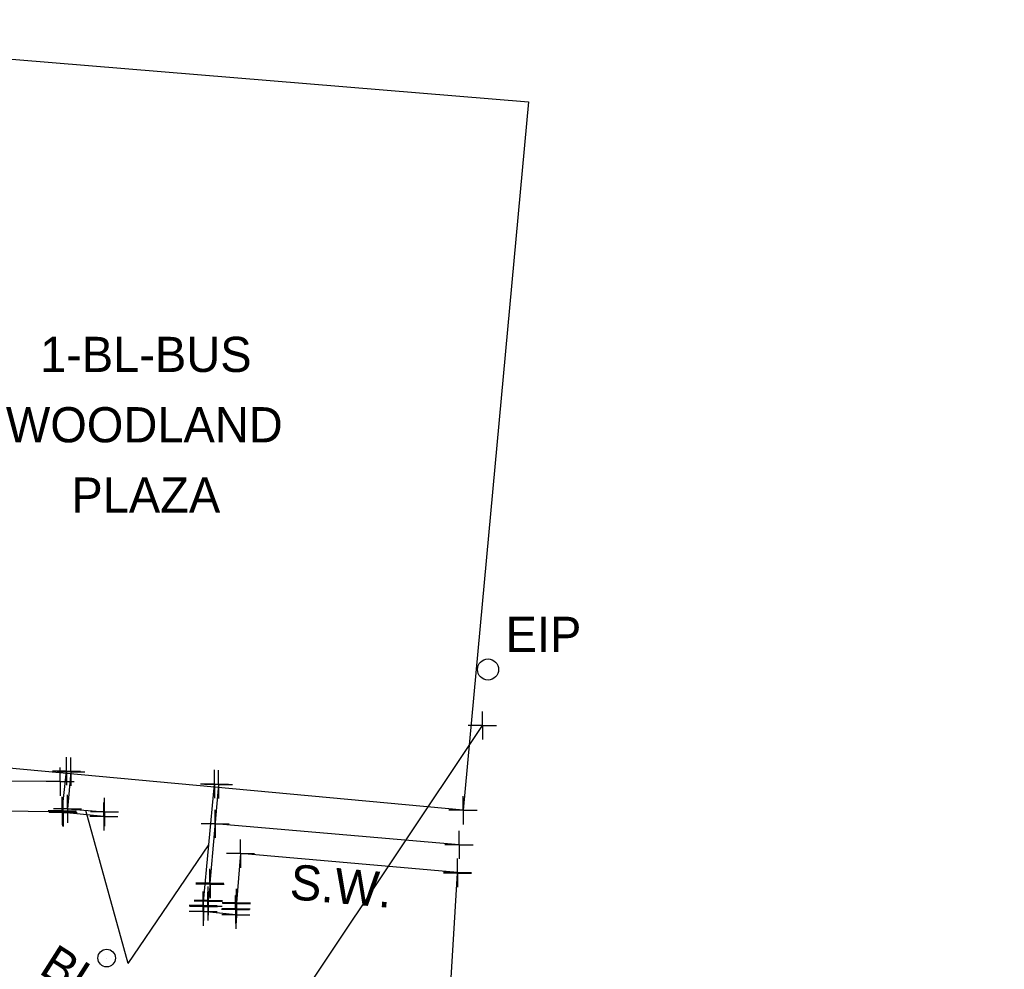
# Model space of a CAD drawing. Extents: x 0 to 1944463, y 0 to 420651.
# Drawn here: x 1942891.8 to 1943031.9, y 417869.6 to 418004.6 of the extents above; entities that cross this region are included whole.
import ezdxf

# ---------------------------------------------------------------- set-up
doc = ezdxf.new("R2010")
doc.units = 0
for name, color, linetype in [('SUR - DTM - Breaklines', 7, 'Continuous'), ('SUR - DTM - Breaklines - Points - Locators', 7, 'Continuous'), ('SUR - DTM - Spot Points - Locators', 7, 'Continuous'), ('SUR - NON-TRAN - Buildings', 7, 'Continuous'), ('SUR - NON-TRAN - Buildings - Points - Locators', 7, 'Continuous'), ('SUR - NON-TRAN - Buildings Text', 7, 'Continuous'), ('SUR - NON-TRAN - Features', 7, 'Continuous'), ('SUR - NON-TRAN - Features - Points - Locators', 7, 'Continuous'), ('SUR - NON-TRAN - Features Text', 7, 'Continuous'), ('SUR - PROPERTY - Property Markers', 7, 'Continuous'), ('SUR - TRAN - Features', 7, 'Continuous'), ('SUR - TRAN - Features - Points - Locators', 7, 'Continuous'), ('SUR - UTL - Overhead Wire Crossings', 7, 'Continuous'), ('SUR - UTL - Overhead Wire Crossings - Points - Locators', 7, 'Continuous')]:
    doc.layers.add(name, color=color, linetype=linetype)

msp = doc.modelspace()

# ---------------------------------------------------------------- linework, layer by layer
at = {"layer": 'SUR - DTM - Breaklines'}
for points in [[(1942903.8, 417891.31), (1942898.03, 417891.89), (1942897.89, 417892.1), (1942898.5, 417897.74)], [(1942920.11, 417895.87), (1942918.88, 417881.84), (1942918.91, 417881.69), (1942918.67, 417879.34), (1942918.67, 417879.26), (1942918.62, 417878.53)]]:
    msp.add_lwpolyline(points, dxfattribs=at)
at = {"layer": 'SUR - DTM - Breaklines - Points - Locators'}
for p, q in [((1942898.5, 417897.74), (1942898.5, 417899.74)), ((1942898.5, 417897.74), (1942896.5, 417897.74)), ((1942898.5, 417897.74), (1942900.5, 417897.74)), ((1942898.5, 417897.74), (1942898.5, 417895.74)), ((1942920.11, 417895.87), (1942920.11, 417897.87)), ((1942920.11, 417895.87), (1942918.11, 417895.87)), ((1942920.11, 417895.87), (1942922.11, 417895.87)), ((1942920.11, 417895.87), (1942920.11, 417893.87)), ((1942897.89, 417892.1), (1942897.89, 417894.1)), ((1942898.03, 417891.89), (1942898.03, 417893.89)), ((1942903.8, 417891.31), (1942903.8, 417893.31)), ((1942897.89, 417892.1), (1942895.89, 417892.1)), ((1942898.03, 417891.89), (1942896.03, 417891.89)), ((1942897.89, 417892.1), (1942899.89, 417892.1)), ((1942897.89, 417892.1), (1942897.89, 417890.1)), ((1942898.03, 417891.89), (1942900.03, 417891.89)), ((1942898.03, 417891.89), (1942898.03, 417889.89)), ((1942903.8, 417891.31), (1942901.8, 417891.31)), ((1942903.8, 417891.31), (1942905.8, 417891.31)), ((1942903.8, 417891.31), (1942903.8, 417889.31)), ((1942918.88, 417881.84), (1942918.88, 417883.84)), ((1942918.91, 417881.69), (1942918.91, 417883.69)), ((1942918.88, 417881.84), (1942916.88, 417881.84)), ((1942918.91, 417881.69), (1942916.91, 417881.69)), ((1942918.67, 417879.34), (1942918.67, 417881.34)), ((1942918.67, 417879.26), (1942918.67, 417881.26)), ((1942918.88, 417881.84), (1942920.88, 417881.84)), ((1942918.88, 417881.84), (1942918.88, 417879.84)), ((1942918.91, 417881.69), (1942920.91, 417881.69)), ((1942918.91, 417881.69), (1942918.91, 417879.69)), ((1942918.67, 417879.34), (1942916.67, 417879.34)), ((1942918.67, 417879.26), (1942916.67, 417879.26)), ((1942918.62, 417878.53), (1942918.62, 417880.53)), ((1942918.67, 417879.34), (1942920.67, 417879.34)), ((1942918.67, 417879.34), (1942918.67, 417877.34)), ((1942918.67, 417879.26), (1942920.67, 417879.26)), ((1942918.67, 417879.26), (1942918.67, 417877.26)), ((1942918.62, 417878.53), (1942916.62, 417878.53)), ((1942918.62, 417878.53), (1942920.62, 417878.53)), ((1942918.62, 417878.53), (1942918.62, 417876.53))]:
    msp.add_line(p, q, dxfattribs=at)
at = {"layer": 'SUR - DTM - Spot Points - Locators'}
msp.add_line((1942904.22, 417871.16), (1942904.22, 417871.16), dxfattribs=at)
msp.add_circle((1942904.21, 417871.17), 1.25, dxfattribs=at)
at = {"layer": 'SUR - NON-TRAN - Buildings'}
msp.add_lwpolyline([(1942954.9, 417892.18), (1942856.97, 417901.23), (1942856.04, 417902.23), (1942856.11, 417903.16), (1942856.72, 417903.14), (1942864.84, 418001.13), (1942964.21, 417992.89)], close=True, dxfattribs=at)
at = {"layer": 'SUR - NON-TRAN - Buildings - Points - Locators'}
for q in [(1942954.9, 417894.18), (1942952.9, 417892.18), (1942956.9, 417892.18), (1942954.9, 417890.18)]:
    msp.add_line((1942954.9, 417892.18), q, dxfattribs=at)
at = {"layer": 'SUR - NON-TRAN - Features'}
for points in [[(1942897.92, 417891.94), (1942849.1, 417892.44), (1942840.15, 417898.52), (1942826.26, 417915.06), (1942801.69, 417944.46), (1942786.47, 417977.69), (1942788.63, 418004.59)], [(1942897.61, 417896.26), (1942849.2, 417896.39), (1942849.2, 417899.01), (1942841.88, 417900.04), (1942844.3, 417902.13), (1942830.35, 417918.22), (1942805.44, 417947.15), (1942791.55, 417977.18), (1942794.14, 418004.51)], [(1942899.12, 417897.67), (1942898.65, 417892.4), (1942903.89, 417891.94)], [(1942917.94, 417878.66), (1942919.54, 417895.92)], [(1942954.33, 417887.28), (1942919.63, 417890.25)], [(1942954.12, 417883.34), (1942923.25, 417886.02), (1942922.66, 417879.01), (1942922.68, 417878.91), (1942922.61, 417878.16), (1942922.55, 417878.08), (1942922.58, 417877.31), (1942917.93, 417877.77), (1942917.99, 417878.51)]]:
    msp.add_lwpolyline(points, dxfattribs=at)
at = {"layer": 'SUR - NON-TRAN - Features - Points - Locators'}
for p, q in [((1942899.12, 417897.67), (1942899.12, 417899.67)), ((1942899.12, 417897.67), (1942897.12, 417897.67)), ((1942897.61, 417896.26), (1942897.61, 417898.26)), ((1942899.12, 417897.67), (1942901.12, 417897.67)), ((1942899.12, 417897.67), (1942899.12, 417895.67)), ((1942919.54, 417895.92), (1942919.54, 417897.92)), ((1942897.61, 417896.26), (1942895.61, 417896.26)), ((1942897.61, 417896.26), (1942899.61, 417896.26)), ((1942897.61, 417896.26), (1942897.61, 417894.26)), ((1942919.54, 417895.92), (1942917.54, 417895.92)), ((1942919.54, 417895.92), (1942921.54, 417895.92)), ((1942919.54, 417895.92), (1942919.54, 417893.92)), ((1942897.92, 417891.94), (1942897.92, 417893.94)), ((1942898.65, 417892.4), (1942898.65, 417894.4)), ((1942903.89, 417891.94), (1942903.89, 417893.94)), ((1942897.92, 417891.94), (1942895.92, 417891.94)), ((1942898.65, 417892.4), (1942896.65, 417892.4)), ((1942897.92, 417891.94), (1942899.92, 417891.94)), ((1942897.92, 417891.94), (1942897.92, 417889.94)), ((1942898.65, 417892.4), (1942900.65, 417892.4)), ((1942898.65, 417892.4), (1942898.65, 417890.4)), ((1942903.89, 417891.94), (1942901.89, 417891.94)), ((1942903.89, 417891.94), (1942905.89, 417891.94)), ((1942903.89, 417891.94), (1942903.89, 417889.94)), ((1942919.63, 417890.25), (1942919.63, 417892.25)), ((1942919.63, 417890.25), (1942917.63, 417890.25)), ((1942919.63, 417890.25), (1942921.63, 417890.25)), ((1942919.63, 417890.25), (1942919.63, 417888.25)), ((1942954.33, 417887.28), (1942954.33, 417889.28)), ((1942923.25, 417886.02), (1942923.25, 417888.02)), ((1942954.33, 417887.28), (1942952.33, 417887.28)), ((1942954.33, 417887.28), (1942956.33, 417887.28)), ((1942954.33, 417887.28), (1942954.33, 417885.28)), ((1942923.25, 417886.02), (1942921.25, 417886.02)), ((1942923.25, 417886.02), (1942925.25, 417886.02)), ((1942923.25, 417886.02), (1942923.25, 417884.02)), ((1942954.12, 417883.34), (1942954.12, 417885.34)), ((1942954.12, 417883.34), (1942952.12, 417883.34)), ((1942954.12, 417883.34), (1942956.12, 417883.34)), ((1942954.12, 417883.34), (1942954.12, 417881.34)), ((1942917.94, 417878.66), (1942917.94, 417880.66)), ((1942922.66, 417879.01), (1942922.66, 417881.01)), ((1942922.68, 417878.91), (1942922.68, 417880.91)), ((1942917.93, 417877.77), (1942917.93, 417879.77)), ((1942917.99, 417878.51), (1942917.99, 417880.51)), ((1942922.55, 417878.08), (1942922.55, 417880.08)), ((1942922.58, 417877.31), (1942922.58, 417879.31)), ((1942922.61, 417878.16), (1942922.61, 417880.16)), ((1942917.93, 417877.77), (1942915.93, 417877.77)), ((1942917.94, 417878.66), (1942915.94, 417878.66)), ((1942917.99, 417878.51), (1942915.99, 417878.51)), ((1942917.93, 417877.77), (1942919.93, 417877.77)), ((1942917.93, 417877.77), (1942917.93, 417875.77)), ((1942917.94, 417878.66), (1942919.94, 417878.66)), ((1942917.94, 417878.66), (1942917.94, 417876.66)), ((1942917.99, 417878.51), (1942919.99, 417878.51)), ((1942917.99, 417878.51), (1942917.99, 417876.51)), ((1942922.55, 417878.08), (1942920.55, 417878.08)), ((1942922.61, 417878.16), (1942920.61, 417878.16)), ((1942922.66, 417879.01), (1942920.66, 417879.01)), ((1942922.68, 417878.91), (1942920.68, 417878.91)), ((1942922.55, 417878.08), (1942924.55, 417878.08)), ((1942922.55, 417878.08), (1942922.55, 417876.08)), ((1942922.61, 417878.16), (1942924.61, 417878.16)), ((1942922.61, 417878.16), (1942922.61, 417876.16)), ((1942922.66, 417879.01), (1942924.66, 417879.01)), ((1942922.66, 417879.01), (1942922.66, 417877.01)), ((1942922.68, 417878.91), (1942924.68, 417878.91)), ((1942922.68, 417878.91), (1942922.68, 417876.91)), ((1942922.58, 417877.31), (1942920.58, 417877.31)), ((1942922.58, 417877.31), (1942924.58, 417877.31)), ((1942922.58, 417877.31), (1942922.58, 417875.31))]:
    msp.add_line(p, q, dxfattribs=at)
at = {"layer": 'SUR - NON-TRAN - Features Text'}
for q in [(1942901.27, 417892.17), (1942918.74, 417887.29)]:
    msp.add_line((1942907.25, 417870.42), q, dxfattribs=at)
at = {"layer": 'SUR - PROPERTY - Property Markers'}
msp.add_circle((1942958.45, 417912.2), 1.5, dxfattribs=at)
at = {"layer": 'SUR - TRAN - Features'}
msp.add_lwpolyline([(1943002.66, 417751.27), (1943031.88, 417795), (1942996.66, 417820.96), (1942952.15, 417851.11), (1942954.1, 417883.23)], dxfattribs=at)
at = {"layer": 'SUR - TRAN - Features - Points - Locators'}
for q in [(1942954.1, 417885.23), (1942952.1, 417883.23), (1942956.1, 417883.23), (1942954.1, 417881.23)]:
    msp.add_line((1942954.1, 417883.23), q, dxfattribs=at)
at = {"layer": 'SUR - UTL - Overhead Wire Crossings'}
msp.add_lwpolyline([(1942849.57, 417742.45), (1942957.65, 417904.24)], dxfattribs=at)
at = {"layer": 'SUR - UTL - Overhead Wire Crossings - Points - Locators'}
for q in [(1942957.65, 417906.24), (1942955.65, 417904.24), (1942959.65, 417904.24), (1942957.65, 417902.24)]:
    msp.add_line((1942957.65, 417904.24), q, dxfattribs=at)

# ---------------------------------------------------------------- texts
at = {"layer": 'SUR - NON-TRAN - Buildings Text'}
for s, p in [('1-BL-BUS', (1942894.73, 417954.5)), ('WOODLAND', (1942889.88, 417944.5)), ('PLAZA', (1942899.19, 417934.5))]:
    msp.add_text(s, height=5, dxfattribs=at).set_placement(p)
at = {"layer": 'SUR - NON-TRAN - Features Text'}
for s, rotation, p in [('S.W.', 355.0283, (1942930.14, 417879.56)), ('BLOCK ', 327.5548, (1942894.4, 417869.1))]:
    msp.add_text(s, height=5, rotation=rotation, dxfattribs=at).set_placement(p)
at = {"layer": 'SUR - PROPERTY - Property Markers'}
msp.add_text('EIP', height=5, dxfattribs=at).set_placement((1942960.95, 417914.7))

doc.saveas('drawing.dxf')
